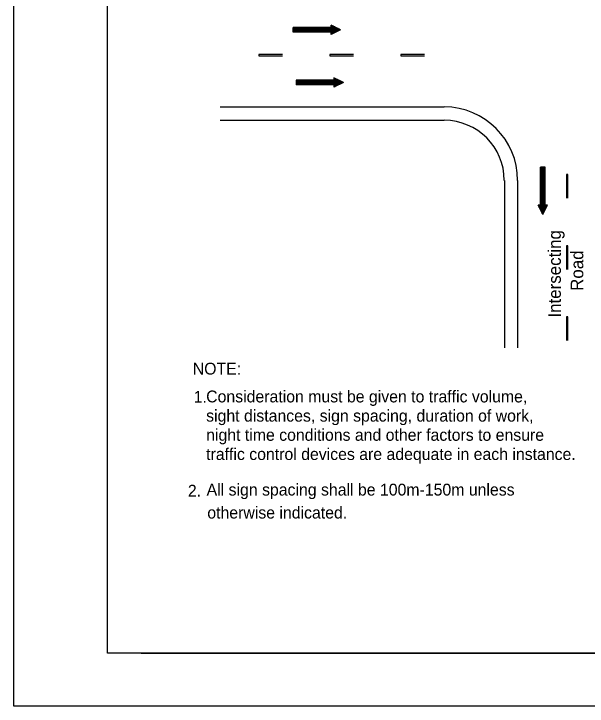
# Model space of a CAD drawing. Extents: x 2111 to 2327, y 208 to 487.
# Drawn here: x 2111.3 to 2228.5, y 208.2 to 349.6 of the extents above; entities that cross this region are included whole.
import ezdxf

# ---------------------------------------------------------------- set-up
doc = ezdxf.new("R2010")
doc.units = 0
for name, color, linetype in [('Level 10', 7, 'Continuous'), ('Level 2', 7, 'Continuous'), ('Level 22', 7, 'Continuous'), ('Level 60', 7, 'Continuous')]:
    doc.layers.add(name, color=color, linetype=linetype)

msp = doc.modelspace()

# ---------------------------------------------------------------- linework, layer by layer
at = {"layer": 'Level 10'}
for p, q in [((2176.15, 346.79), (2168.41, 346.79)), ((2168.41, 345.82), (2168.41, 346.79)), ((2177.12, 346.79), (2168.41, 346.79)), ((2177.36, 346.67), (2168.41, 346.67)), ((2177.6, 346.55), (2168.41, 346.55)), ((2177.85, 346.43), (2168.41, 346.43)), ((2178.09, 346.31), (2176.15, 347.28)), ((2176.15, 346.79), (2176.15, 347.28)), ((2176.39, 347.15), (2176.15, 347.15)), ((2176.64, 347.03), (2176.15, 347.03)), ((2176.88, 346.91), (2176.15, 346.91)), ((2178.09, 346.31), (2168.41, 346.31)), ((2177.85, 346.19), (2168.41, 346.19)), ((2177.6, 346.06), (2168.41, 346.06)), ((2177.36, 345.94), (2168.41, 345.94)), ((2176.15, 345.82), (2168.41, 345.82)), ((2177.12, 345.82), (2168.41, 345.82)), ((2178.09, 346.31), (2176.15, 345.34)), ((2176.15, 345.34), (2176.15, 345.82)), ((2176.88, 345.7), (2176.15, 345.7)), ((2176.64, 345.58), (2176.15, 345.58)), ((2176.39, 345.46), (2176.15, 345.46)), ((2178.67, 335.54), (2176.73, 336.5)), ((2176.73, 336.5), (2176.73, 336.02)), ((2176.73, 336.02), (2168.99, 336.02)), ((2168.99, 336.02), (2168.99, 335.05)), ((2177.7, 336.02), (2168.99, 336.02)), ((2177.94, 335.9), (2168.99, 335.9)), ((2178.18, 335.78), (2168.99, 335.78)), ((2178.42, 335.66), (2168.99, 335.66)), ((2178.67, 335.54), (2168.99, 335.54)), ((2178.42, 335.42), (2168.99, 335.42)), ((2178.18, 335.3), (2168.99, 335.3)), ((2177.94, 335.17), (2168.99, 335.17)), ((2176.73, 335.05), (2168.99, 335.05)), ((2177.7, 335.05), (2168.99, 335.05)), ((2176.97, 336.38), (2176.73, 336.38)), ((2177.21, 336.26), (2176.73, 336.26)), ((2177.46, 336.14), (2176.73, 336.14)), ((2178.67, 335.54), (2176.73, 334.57)), ((2176.73, 335.05), (2176.73, 334.57)), ((2177.46, 334.93), (2176.73, 334.93)), ((2177.21, 334.81), (2176.73, 334.81)), ((2176.97, 334.69), (2176.73, 334.69)), ((2153.49, 330.56), (2199.27, 330.56)), ((2153.49, 327.83), (2199.27, 327.83)), ((2218.94, 310.51), (2218.94, 318.26)), ((2219.91, 318.26), (2218.94, 318.26)), ((2218.94, 309.55), (2218.94, 318.26)), ((2219.06, 309.3), (2219.06, 318.26)), ((2219.18, 309.06), (2219.18, 318.26)), ((2219.3, 308.82), (2219.3, 318.26)), ((2219.42, 308.58), (2219.42, 318.26)), ((2219.54, 308.82), (2219.54, 318.26)), ((2219.66, 309.06), (2219.66, 318.26)), ((2219.78, 309.3), (2219.78, 318.26)), ((2219.91, 310.51), (2219.91, 318.26)), ((2219.91, 309.55), (2219.91, 318.26)), ((2211.55, 315.56), (2211.55, 281.4)), ((2214.27, 315.56), (2214.27, 281.4)), ((2219.42, 308.58), (2218.45, 310.51)), ((2218.94, 310.51), (2218.45, 310.51)), ((2218.58, 310.27), (2218.58, 310.51)), ((2218.7, 310.03), (2218.7, 310.51)), ((2218.82, 309.79), (2218.82, 310.51)), ((2219.42, 308.58), (2220.39, 310.51)), ((2220.39, 310.51), (2219.91, 310.51)), ((2220.03, 309.79), (2220.03, 310.51)), ((2220.15, 310.03), (2220.15, 310.51)), ((2220.27, 310.27), (2220.27, 310.51))]:
    msp.add_line(p, q, dxfattribs=at)
for radius in [15, 12.27]:
    msp.add_arc((2199.27, 315.56), radius, 0, 90, dxfattribs=at)
at = {"layer": 'Level 2'}
for p, q in [((2166.2, 341.3), (2161.36, 341.3)), ((2161.36, 341.3), (2161.36, 341.01)), ((2161.36, 341.01), (2166.2, 341.01)), ((2180.71, 341.3), (2175.87, 341.3)), ((2175.87, 341.3), (2175.87, 341.01)), ((2175.87, 341.01), (2180.71, 341.01)), ((2195.22, 341.3), (2190.39, 341.3)), ((2190.39, 341.3), (2190.39, 341.01)), ((2190.39, 341.01), (2195.22, 341.01)), ((2224.26, 316.74), (2224.26, 311.9)), ((2224.55, 316.74), (2224.26, 316.74)), ((2224.55, 311.9), (2224.55, 316.74)), ((2224.26, 302.23), (2224.26, 297.39)), ((2224.55, 302.23), (2224.26, 302.23)), ((2224.55, 297.39), (2224.55, 302.23)), ((2224.26, 287.71), (2224.26, 282.87)), ((2224.55, 287.71), (2224.26, 287.71)), ((2224.55, 282.87), (2224.55, 287.71))]:
    msp.add_line(p, q, dxfattribs=at)
at = {"layer": 'Level 22'}
msp.add_line((2137.32, 219.02), (2317.32, 219.02), dxfattribs=at)
at = {"layer": 'Level 60'}
for points in [[(2111.32, 487.21), (2327.32, 487.21), (2327.32, 208.21), (2111.32, 208.21)], [(2130.44, 476.4), (2317.32, 476.4), (2317.32, 219.02), (2130.44, 219.02)]]:
    msp.add_lwpolyline(points, close=True, dxfattribs=at)

# ---------------------------------------------------------------- texts
at = {"layer": 'Level 10'}
for s, p in [('Intersecting', (2223.1, 287.54)), ('Road', (2227.69, 293))]:
    msp.add_text(s, height=2.585, rotation=90, dxfattribs=at).set_placement(p)
for s, p in [('NOTE:', (2147.88, 275.91)), ('1.', (2148.08, 270.16)), ('Consideration must be given to traffic volume,', (2150.62, 270.23)), ('sight distances, sign spacing, duration of work,', (2150.62, 266.31)), ('night time conditions and other factors to ensure', (2150.62, 262.39)), ('traffic control devices are adequate in each instance.', (2150.62, 258.47)), ('2.', (2146.88, 250.99)), ('All sign spacing shall be 100m-150m unless', (2150.71, 251.21)), ('otherwise indicated.', (2150.85, 246.52))]:
    msp.add_text(s, height=2.419, dxfattribs=at).set_placement(p)

doc.saveas('drawing.dxf')
